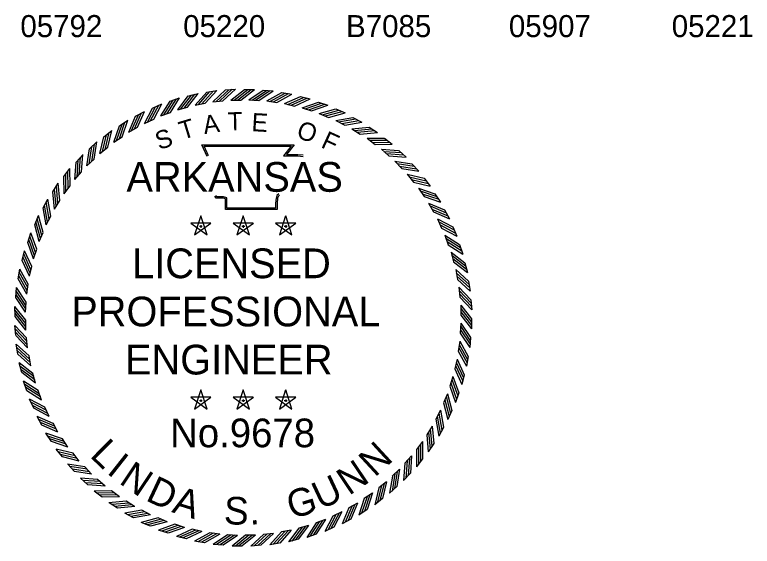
# Model space of a CAD drawing. Extents: x -12863 to 18921, y -8840 to 11152.
# Drawn here: x 13229 to 17244, y -8799 to -5907 of the extents above; entities that cross this region are included whole.
import ezdxf

# ---------------------------------------------------------------- set-up
doc = ezdxf.new("R2010")
doc.units = 0
doc.layers.add('Level 50', color=7, linetype='Continuous')
doc.layers.add('Level 52', color=7, linetype='Continuous')

msp = doc.modelspace()

# ---------------------------------------------------------------- linework, layer by layer
at = {"layer": 'Level 52'}
for p, q in [((14174, -6349), (14226.7, -6335.2)), ((14274.6, -6328.5), (14328.3, -6319)), ((14376.6, -6316.3), (14430.9, -6311.3)), ((14479.8, -6313.2), (14534.3, -6313.2)), ((14581.9, -6317.3), (14636.2, -6321.3)), ((14683.7, -6330.6), (14737.5, -6339)), ((14075.4, -6377.8), (14126.8, -6359.7)), ((14307.9, -6380.8), (14362.3, -6375.8)), ((14405.4, -6371.2), (14460.1, -6371.2)), ((14503.4, -6369.7), (14557.9, -6373.7)), ((14601.2, -6376.3), (14655.2, -6384.8)), ((14784.1, -6352.1), (14837.1, -6365)), ((14882.4, -6382), (14934.1, -6399.2)), ((13979.6, -6414.7), (14029.2, -6392.3)), ((14116.8, -6424), (14169.7, -6410.1)), ((14211.5, -6398.5), (14265.3, -6389)), ((14698.2, -6390.9), (14751.2, -6403.8)), ((14793.5, -6413.5), (14845.4, -6430.7)), ((14977.9, -6419.8), (15028, -6441.2)), ((13887.1, -6459.3), (13934.7, -6432.9)), ((14024.7, -6457.3), (14076.1, -6439.1)), ((14886.7, -6443.8), (14936.9, -6465.3)), ((13798.6, -6511.4), (13843.9, -6481.2)), ((13935.5, -6498.1), (13985.3, -6475.7)), ((14977.1, -6481.8), (15025.4, -6507.4)), ((15069.9, -6465.4), (15118.1, -6490.8)), ((13714.7, -6570.7), (13757.3, -6536.8)), ((13850.1, -6546), (13897.8, -6519.6)), ((15064, -6527.1), (15110, -6556.6)), ((15157.9, -6518.4), (15203.8, -6547.8)), ((13768.8, -6600.9), (13814.3, -6570.6)), ((15146.9, -6579.4), (15190.3, -6612.6)), ((15241.2, -6578.5), (15284.5, -6611.6)), ((13636, -6636.7), (13675.7, -6599.4)), ((13692.4, -6662.3), (13735.2, -6628.4)), ((15225.2, -6638.4), (15265.7, -6675)), ((15319.2, -6645.3), (15359.6, -6681.8)), ((13563, -6708.9), (13599.5, -6668.5)), ((13621.4, -6729.8), (13661.2, -6692.5)), ((15298.3, -6703.7), (15335.7, -6743.5)), ((13496.2, -6787), (13529.2, -6743.7)), ((15391.5, -6718.3), (15428.7, -6758)), ((13556.1, -6803), (13592.7, -6762.4)), ((15365.8, -6774.7), (15399.7, -6817.5)), ((13436.1, -6870.2), (13465.5, -6824.4)), ((15457.4, -6797), (15491.3, -6839.7)), ((13497.1, -6881.2), (13530.3, -6837.8)), ((15427.2, -6851.1), (15457.5, -6896.6)), ((15516.7, -6880.9), (15546.9, -6926.2)), ((13383, -6958.2), (13408.5, -6910)), ((13444.8, -6964.1), (13474.3, -6918.1)), ((15482.1, -6932.4), (15508.5, -6980.1)), ((15568.8, -6969.4), (15595.2, -7017)), ((13337.5, -7050.2), (13358.9, -7000.1)), ((13399.5, -7051), (13425.1, -7002.8)), ((14241.7, -7000.7), (14207.6, -7105.3)), ((14275.7, -7105.2), (14241.8, -7000.6)), ((14472.8, -7000.7), (14438.7, -7105.3)), ((14506.8, -7105.2), (14472.9, -7000.6)), ((14703.9, -7000.7), (14669.8, -7105.3)), ((14737.9, -7105.2), (14704, -7000.6)), ((15530.1, -7017.8), (15552.5, -7067.6)), ((14296.6, -7040.6), (14186.7, -7040.5)), ((14186.7, -7040.6), (14275.7, -7105.4)), ((14207.7, -7105.2), (14296.8, -7040.7)), ((14233.9, -7058.2), (14250.2, -7058.2)), ((14241.8, -7052.3), (14241.8, -7066.1)), ((14527.8, -7040.6), (14417.8, -7040.5)), ((14417.9, -7040.6), (14506.8, -7105.4)), ((14438.8, -7105.2), (14527.9, -7040.7)), ((14465, -7058.2), (14481.3, -7058.2)), ((14472.9, -7052.3), (14472.9, -7066.1)), ((14758.9, -7040.6), (14648.9, -7040.5)), ((14649, -7040.6), (14737.9, -7105.4)), ((14670, -7105.2), (14759, -7040.7)), ((14696.1, -7058.2), (14712.4, -7058.2)), ((14704, -7052.3), (14704, -7066.1)), ((15613.5, -7061.9), (15635.8, -7111.5)), ((13299.6, -7145.7), (13316.9, -7094)), ((13361.5, -7141.4), (13383, -7091.2)), ((15570.9, -7107), (15589.1, -7158.4)), ((13331.2, -7234.6), (13348.4, -7182.8)), ((15650.3, -7157.7), (15668.5, -7209.1)), ((13269.8, -7244), (13282.7, -7191.1)), ((15604.1, -7199.2), (15618, -7252)), ((15679.1, -7256.3), (15693, -7309)), ((13248.2, -7344.4), (13256.7, -7290.6)), ((13308.6, -7330), (13321.5, -7276.9)), ((15629.7, -7293.8), (15639.1, -7347.6)), ((13294, -7426.9), (13302.5, -7372.9)), ((15699.7, -7356.9), (15709.1, -7410.6)), ((13235, -7446.3), (13239, -7391.9)), ((15647.3, -7390.2), (15652.3, -7444.6)), ((15711.9, -7458.9), (15716.9, -7513.2)), ((13230.3, -7548.9), (13229.8, -7494.4)), ((13287.4, -7524.7), (13291.4, -7470.2)), ((15656.9, -7487.7), (15657.4, -7542.4)), ((13288.9, -7622.7), (13288.4, -7568.1)), ((15658.4, -7585.7), (15654.4, -7640.2)), ((15715.6, -7561.6), (15716.1, -7616)), ((13234, -7651.5), (13229, -7597.3)), ((13298.5, -7720.2), (13293.5, -7665.9)), ((15710.8, -7664.2), (15706.8, -7718.5)), ((13246.2, -7753.5), (13236.7, -7699.8)), ((15651.9, -7683.5), (15643.4, -7737.5)), ((13316.2, -7816.7), (13306.7, -7762.9)), ((15637.2, -7780.5), (15624.3, -7833.5)), ((15697.6, -7766), (15689.1, -7819.8)), ((13266.7, -7854.1), (13252.9, -7801.4)), ((13341.7, -7911.3), (13327.8, -7858.5)), ((15676, -7866.4), (15663.1, -7919.4)), ((13295.5, -7952.7), (13277.4, -7901.3)), ((15614.7, -7875.8), (15597.4, -7927.7)), ((14241.7, -7948.3), (14207.6, -8052.9)), ((14275.7, -8052.8), (14241.8, -7948.2)), ((14472.8, -7948.3), (14438.7, -8052.9)), ((14506.8, -8052.8), (14472.9, -7948.2)), ((14703.9, -7948.3), (14669.8, -8052.9)), ((14737.9, -8052.8), (14704, -7948.2)), ((13375, -8003.5), (13356.8, -7952)), ((14296.6, -7988.2), (14186.7, -7988.1)), ((14186.7, -7988.2), (14275.7, -8053)), ((14207.7, -8052.8), (14296.8, -7988.3)), ((14527.8, -7988.2), (14417.8, -7988.1)), ((14417.9, -7988.2), (14506.8, -8053)), ((14438.8, -8052.8), (14527.9, -7988.3)), ((14758.9, -7988.2), (14648.9, -7988.1)), ((14649, -7988.2), (14737.9, -8053)), ((14670, -8052.8), (14759, -7988.3)), ((15584.3, -7969), (15562.8, -8019.2)), ((15646.2, -7964.7), (15629, -8016.4)), ((13332.4, -8048.6), (13310, -7998.9)), ((14233.9, -8005.8), (14250.2, -8005.8)), ((14241.8, -7999.9), (14241.8, -8013.7)), ((14465, -8005.8), (14481.3, -8005.8)), ((14472.9, -7999.9), (14472.9, -8013.7)), ((14696.1, -8005.8), (14712.4, -8005.8)), ((14704, -7999.9), (14704, -8013.7)), ((13415.7, -8092.6), (13393.3, -8042.8)), ((15546.3, -8059.4), (15520.8, -8107.7)), ((15608.4, -8060.2), (15586.9, -8110.3)), ((13377, -8141.1), (13350.6, -8093.4)), ((13463.7, -8178.1), (13437.3, -8130.3)), ((15501, -8146.3), (15471.6, -8192.3)), ((13429.1, -8229.6), (13398.9, -8184.2)), ((15562.8, -8152.2), (15537.3, -8200.4)), ((13518.6, -8259.3), (13488.3, -8213.9)), ((15448.7, -8229.2), (15415.6, -8272.6)), ((13488.4, -8313.5), (13454.5, -8270.8)), ((15509.8, -8240.2), (15480.4, -8286.1)), ((13580, -8335.7), (13546.1, -8292.9)), ((15389.7, -8307.5), (15353.1, -8348)), ((15449.7, -8323.5), (15416.6, -8366.8)), ((13554.4, -8392.2), (13517.1, -8352.4)), ((13647.5, -8406.8), (13610.2, -8366.9)), ((15324.5, -8380.6), (15284.6, -8418)), ((13626.6, -8465.2), (13586.2, -8428.6)), ((15382.9, -8401.5), (15346.3, -8441.9)), ((13720.7, -8472), (13680.1, -8435.4)), ((15253.4, -8448.1), (15210.6, -8482.1)), ((13704.7, -8532), (13661.4, -8498.9)), ((13798.9, -8531), (13755.5, -8497.9)), ((15177, -8509.5), (15131.5, -8539.8)), ((15309.9, -8473.8), (15270.1, -8511)), ((15231.2, -8539.7), (15188.5, -8573.6)), ((13787.9, -8592.1), (13742.1, -8562.7)), ((13881.8, -8583.3), (13835.8, -8553.9)), ((15095.8, -8564.4), (15048, -8590.8)), ((13875.9, -8645.1), (13827.7, -8619.6)), ((13968.7, -8628.6), (13920.5, -8603.1)), ((15010.3, -8612.4), (14960.5, -8634.8)), ((15147.3, -8599), (15101.9, -8629.2)), ((13967.9, -8690.7), (13917.8, -8669.2)), ((14059.1, -8666.6), (14008.9, -8645.1)), ((14921.2, -8653.2), (14869.7, -8671.4)), ((15058.8, -8651.1), (15011.1, -8677.5)), ((14063.4, -8728.5), (14011.7, -8711.3)), ((14152.3, -8697), (14100.5, -8679.7)), ((14247.7, -8719.6), (14194.6, -8706.6)), ((14734.3, -8712), (14680.6, -8721.4)), ((14829, -8686.4), (14776.2, -8700.3)), ((14966.3, -8695.8), (14916.6, -8718.1)), ((14161.7, -8758.3), (14108.8, -8745.4)), ((14344.6, -8734.2), (14290.6, -8725.7)), ((14442.4, -8740.7), (14387.9, -8736.7)), ((14540.4, -8739.2), (14485.8, -8739.7)), ((14637.9, -8729.6), (14583.6, -8734.6)), ((14870.4, -8732.6), (14819, -8750.8)), ((14262.1, -8779.9), (14208.3, -8771.4)), ((14364, -8793.1), (14309.6, -8789.1)), ((14671.2, -8782), (14617.5, -8791.4)), ((14771.8, -8761.4), (14719.1, -8775.3)), ((14466.6, -8797.9), (14412.1, -8798.4)), ((14569.2, -8794.2), (14515, -8799.2))]:
    msp.add_line(p, q, dxfattribs=at)
for points in [[(14152, -6414.6), (14209.1, -6339.6)], [(14169.6, -6410.1), (14226.7, -6335.1)], [(14211.4, -6398.5), (14274.6, -6328.5)], [(14228.7, -6395.7), (14291.9, -6325.6)], [(14247.3, -6392), (14310.4, -6321.9)], [(14265.2, -6389), (14328.3, -6319)], [(14307.8, -6380.9), (14376.5, -6316.3)], [(14325.3, -6379.4), (14394, -6314.9)], [(14344.1, -6377.3), (14412.8, -6312.7)], [(14362.2, -6375.8), (14430.9, -6311.2)], [(14405.4, -6371.3), (14479.7, -6313.3)], [(14422.9, -6371.4), (14497.3, -6313.5)], [(14441.8, -6371), (14516.2, -6313)], [(14460, -6371.2), (14534.3, -6313.2)], [(14503.4, -6369.7), (14581.8, -6317.4)], [(14520.9, -6371.2), (14599.2, -6318.8)], [(14539.8, -6372.2), (14618.2, -6319.8)], [(14557.8, -6373.7), (14636.2, -6321.3)], [(14601.2, -6376.3), (14683.6, -6330.6)], [(14618.5, -6379.2), (14700.9, -6333.5)], [(14637.2, -6381.7), (14719.7, -6336)], [(14655.1, -6384.7), (14737.6, -6339)], [(14024.6, -6457.4), (14075.4, -6377.9)], [(14041.2, -6451.7), (14092, -6372.2)], [(14058.9, -6445), (14109.7, -6365.5)], [(14076.1, -6439.1), (14126.8, -6359.6)], [(14116.8, -6424.1), (14173.9, -6349.1)], [(14133.8, -6419.8), (14190.9, -6344.8)], [(14698.1, -6390.9), (14784, -6352.2)], [(14715.1, -6395.2), (14801, -6356.5)], [(14733.6, -6399.3), (14819.5, -6360.5)], [(14751.2, -6403.8), (14837.1, -6365)], [(14793.5, -6413.5), (14882.3, -6382)], [(13935.5, -6498.1), (13979.5, -6414.8)], [(13951.5, -6491.1), (13995.6, -6407.7)], [(13968.6, -6482.9), (14012.7, -6399.6)], [(13985.3, -6475.6), (14029.3, -6392.3)], [(14810, -6419.2), (14898.9, -6387.7)], [(14828.1, -6424.8), (14917, -6393.3)], [(14845.3, -6430.7), (14934.2, -6399.1)], [(14886.6, -6443.9), (14977.8, -6419.8)], [(13850, -6546.1), (13887, -6459.4)], [(13865.4, -6537.8), (13902.4, -6451.1)], [(13881.8, -6528.2), (13918.8, -6441.5)], [(13897.8, -6519.6), (13934.8, -6432.9)], [(14902.7, -6450.9), (14993.9, -6426.8)], [(14920.3, -6458), (15011.4, -6433.9)], [(14936.9, -6465.3), (15028, -6441.2)], [(13783.5, -6591.4), (13813.2, -6501.9)], [(13799, -6580.6), (13828.7, -6491.1)], [(13814.2, -6570.6), (13843.9, -6481.2)], [(14977, -6481.8), (15069.8, -6465.4)], [(14992.4, -6490.2), (15085.3, -6473.7)], [(15009.4, -6498.7), (15102.2, -6482.2)], [(15025.3, -6507.3), (15118.1, -6490.8)], [(13735.2, -6628.4), (13757.4, -6536.8)], [(13768.8, -6601), (13798.5, -6511.5)], [(15063.9, -6527.1), (15157.8, -6518.4)], [(15078.6, -6536.7), (15172.5, -6528)], [(15094.8, -6546.6), (15188.6, -6537.8)], [(13692.4, -6662.4), (13714.6, -6570.8)], [(13706.3, -6651.6), (13728.5, -6560)], [(13720.8, -6639.5), (13743, -6547.9)], [(15110, -6556.5), (15203.8, -6547.7)], [(15146.8, -6579.4), (15241.1, -6578.5)], [(13634.3, -6718), (13648.8, -6624.9)], [(13647.8, -6704.8), (13662.4, -6611.6)], [(13661.1, -6692.5), (13675.7, -6599.3)], [(14276.8, -6677.9), (14247.8, -6615), (14750.3, -6614.7), (14708.3, -6667.5), (14742.4, -6667), (14770.9, -6666.7), (14799.4, -6669.8)], [(14284, -6674.6), (14260.2, -6623), (14733.7, -6622.7), (14691.6, -6675.6), (14742.5, -6675), (14770.6, -6674.6), (14798.6, -6677.7)], [(15160.6, -6590.2), (15254.9, -6589.2)], [(15175.9, -6601.4), (15270.2, -6600.4)], [(15190.3, -6612.5), (15284.5, -6611.6)], [(13621.4, -6729.9), (13635.9, -6636.8)], [(15225.1, -6638.4), (15319.1, -6645.2)], [(15238, -6650.3), (15332, -6657.1)], [(15252.3, -6662.7), (15346.3, -6669.5)], [(13568, -6790.1), (13574.8, -6696.1)], [(13580.4, -6775.8), (13587.2, -6681.8)], [(13592.7, -6762.5), (13599.5, -6668.4)], [(15265.7, -6675), (15359.7, -6681.8)], [(15298.2, -6703.7), (15391.4, -6718.2)], [(13530.2, -6837.9), (13529.2, -6743.6)], [(13556.1, -6803), (13562.9, -6709)], [(15310.1, -6716.6), (15403.2, -6731.1)], [(15323.4, -6730.1), (15416.5, -6744.7)], [(15335.7, -6743.4), (15428.8, -6758)], [(13507.9, -6867.5), (13506.9, -6773.2)], [(13519.1, -6852.2), (13518.1, -6757.9)], [(15365.7, -6774.7), (15457.4, -6796.9)], [(13474.2, -6918.2), (13465.4, -6824.3)], [(13497.1, -6881.3), (13496.2, -6787.1)], [(15376.5, -6788.6), (15468.1, -6810.8)], [(15388.6, -6803.1), (15480.2, -6825.3)], [(15399.7, -6817.5), (15491.4, -6839.7)], [(13454.4, -6949.5), (13445.7, -6855.7)], [(13464.3, -6933.4), (13455.5, -6839.5)], [(15427.1, -6851.1), (15516.6, -6880.8)], [(15436.7, -6865.8), (15526.2, -6895.5)], [(13444.8, -6964.2), (13436.1, -6870.3)], [(14671.1, -6888.5), (14662.5, -6895.5), (14659.7, -6905.9), (14656.8, -6931.9), (14656.8, -6966.7), (14376.3, -6966.7), (14376.3, -6919.8), (14376.3, -6909.4), (14364.9, -6905.9), (14325, -6905.9), (14317.9, -6895.1)], [(14666, -6882.3), (14655.5, -6890.9), (14651.8, -6904.4), (14648.9, -6931.5), (14648.9, -6958.7), (14384.3, -6958.7), (14384.3, -6919.8), (14384.3, -6903.5), (14366.1, -6897.9), (14329.3, -6897.9), (14324.6, -6890.7)], [(15447.6, -6881.3), (15537, -6911)], [(15457.5, -6896.5), (15547, -6926.2)], [(13407.9, -7035.7), (13391.4, -6942.9)], [(13416.4, -7018.8), (13399.9, -6925.9)], [(13425, -7002.8), (13408.5, -6910)], [(15482, -6932.3), (15568.7, -6969.3)], [(13399.5, -7051.1), (13383.1, -6958.3)], [(15490.4, -6947.7), (15577.1, -6984.7)], [(15499.9, -6964.1), (15586.6, -7001.1)], [(15508.5, -6980.1), (15595.2, -7017.1)], [(13375.7, -7107.9), (13351.6, -7016.7)], [(13383, -7091.2), (13358.9, -7000.1)], [(15530, -7017.8), (15613.4, -7061.8)], [(13361.6, -7141.5), (13337.5, -7050.3)], [(13368.6, -7125.4), (13344.5, -7034.3)], [(15537.1, -7033.8), (15620.4, -7077.9)], [(15545.2, -7050.9), (15628.6, -7095)], [(13348.4, -7182.8), (13316.8, -7094)], [(15552.5, -7067.6), (15635.9, -7111.6)], [(15570.8, -7106.9), (15650.2, -7157.7)], [(13331.2, -7234.7), (13299.7, -7145.8)], [(13336.9, -7218.1), (13305.4, -7129.2)], [(13342.5, -7200), (13310.9, -7111.1)], [(15576.5, -7123.5), (15655.9, -7174.3)], [(15583.2, -7141.2), (15662.6, -7192)], [(15589.1, -7158.4), (15668.5, -7209.1)], [(13312.9, -7313.1), (13274.2, -7227.1)], [(13317, -7294.6), (13278.2, -7208.6)], [(13321.4, -7277), (13282.7, -7191)], [(15604.1, -7199.1), (15679, -7256.2)], [(15608.4, -7216.1), (15683.3, -7273.3)], [(13308.6, -7330.1), (13269.9, -7244.1)], [(15613.6, -7234.3), (15688.6, -7291.4)], [(15618, -7251.9), (15693, -7309)], [(13302.4, -7373), (13256.7, -7290.6)], [(15629.6, -7293.7), (15699.6, -7356.9)], [(13294, -7427), (13248.3, -7344.5)], [(13296.9, -7409.7), (13251.2, -7327.2)], [(13299.4, -7390.9), (13253.7, -7308.5)], [(15632.5, -7311), (15702.5, -7374.2)], [(15636.2, -7329.6), (15706.2, -7392.7)], [(15639.2, -7347.5), (15709.2, -7410.6)], [(13289.9, -7488.4), (13237.5, -7410)], [(13291.4, -7470.3), (13239, -7391.9)], [(15647.2, -7390.1), (15711.8, -7458.8)], [(15648.7, -7407.6), (15713.2, -7476.3)], [(15650.8, -7426.4), (15715.4, -7495.1)], [(13287.4, -7524.8), (13235.1, -7446.4)], [(13288.9, -7507.3), (13236.5, -7428.9)], [(15652.3, -7444.5), (15716.9, -7513.2)], [(13288.4, -7568.2), (13229.7, -7494.3)], [(15656.9, -7487.7), (15715.5, -7561.5)], [(15656.9, -7505.2), (15715.5, -7579)], [(13288.4, -7586.3), (13229.7, -7512.5)], [(13289, -7605.2), (13230.3, -7531.4)], [(15657.5, -7524.1), (15716.1, -7597.9)], [(15657.5, -7542.3), (15716.1, -7616.1)], [(13289, -7622.8), (13230.3, -7549)], [(15658.4, -7585.7), (15710.8, -7664.1)], [(13293.5, -7665.9), (13228.9, -7597.2)], [(13295, -7684), (13230.4, -7615.3)], [(15656, -7622.1), (15708.3, -7700.5)], [(15656.9, -7603.2), (15709.3, -7681.6)], [(13297.1, -7702.8), (13232.6, -7634.1)], [(13298.6, -7720.3), (13234, -7651.6)], [(15654.5, -7640.2), (15706.8, -7718.5)], [(13306.7, -7762.9), (13236.7, -7699.8)], [(15648.9, -7700.8), (15694.7, -7783.2)], [(15651.8, -7683.5), (15697.5, -7765.9)], [(13309.6, -7780.8), (13239.6, -7717.7)], [(13313.3, -7799.4), (13243.3, -7736.3)], [(15643.4, -7737.4), (15689.1, -7819.9)], [(15646.4, -7719.5), (15692.1, -7802)], [(13316.2, -7816.7), (13246.2, -7753.6)], [(15637.2, -7780.4), (15676, -7866.3)], [(13327.8, -7858.5), (13252.8, -7801.4)], [(13332.3, -7876.1), (13257.3, -7819)], [(15628.8, -7815.9), (15667.6, -7901.8)], [(15632.9, -7797.4), (15671.7, -7883.3)], [(13337.5, -7894.3), (13262.5, -7837.2)], [(13341.8, -7911.3), (13266.8, -7854.2)], [(15624.4, -7833.5), (15663.1, -7919.4)], [(13356.8, -7952.1), (13277.3, -7901.3)], [(15608.9, -7892.4), (15640.5, -7981.2)], [(15614.6, -7875.8), (15646.2, -7964.6)], [(13362.6, -7969.2), (13283.2, -7918.5)], [(13369.4, -7986.9), (13289.9, -7936.2)], [(15597.5, -7927.6), (15629, -8016.5)], [(15603.4, -7910.4), (15634.9, -7999.3)], [(13375, -8003.5), (13295.6, -7952.8)], [(15577.2, -7985), (15601.3, -8076.2)], [(15584.3, -7969), (15608.3, -8060.1)], [(13393.3, -8042.9), (13310, -7998.9)], [(13400.6, -8059.5), (13317.3, -8015.5)], [(15562.9, -8019.2), (15587, -8110.4)], [(15570.2, -8002.6), (15594.2, -8093.7)], [(13408.8, -8076.6), (13325.4, -8032.6)], [(13415.8, -8092.7), (13332.5, -8048.6)], [(15546.3, -8059.3), (15562.8, -8152.1)], [(13437.3, -8130.4), (13350.6, -8093.4)], [(13445.9, -8146.3), (13359.2, -8109.3)], [(15520.8, -8107.6), (15537.3, -8200.5)], [(15529.5, -8091.7), (15545.9, -8184.5)], [(15538, -8074.7), (15554.4, -8167.6)], [(13455.5, -8162.7), (13368.7, -8125.7)], [(13463.8, -8178.1), (13377.1, -8141.1)], [(15501, -8146.2), (15509.8, -8240.1)], [(13488.3, -8213.9), (13398.9, -8184.2)], [(15481.6, -8177.1), (15490.3, -8271)], [(15491.4, -8160.9), (15500.2, -8254.8)], [(13498.3, -8229.1), (13408.8, -8199.4)], [(13509.1, -8244.6), (13419.6, -8214.9)], [(13518.7, -8259.3), (13429.2, -8229.6)], [(15448.7, -8229.1), (15449.7, -8323.4)], [(15471.6, -8192.3), (15480.4, -8286.1)], [(13546.1, -8293), (13454.5, -8270.8)], [(15426.8, -8258.3), (15427.7, -8352.5)], [(15437.9, -8243), (15438.9, -8337.2)], [(13557.2, -8307.3), (13465.6, -8285.1)], [(13569.3, -8321.9), (13477.7, -8299.7)], [(15389.7, -8307.4), (15382.9, -8401.4)], [(15415.6, -8272.6), (15416.6, -8366.8)], [(13580.1, -8335.7), (13488.5, -8313.5)], [(15353.2, -8348), (15346.3, -8442)], [(15365.5, -8334.6), (15358.6, -8428.6)], [(15377.8, -8320.3), (15371, -8414.3)], [(13610.2, -8367), (13517, -8352.4)], [(13622.5, -8380.4), (13529.3, -8365.8)], [(13635.7, -8393.9), (13542.6, -8379.3)], [(15324.5, -8380.5), (15309.9, -8473.7)], [(13647.6, -8406.8), (13554.5, -8392.2)], [(13680.2, -8435.5), (13586.1, -8428.6)], [(15284.7, -8418), (15270.1, -8511.1)], [(15298, -8405.7), (15283.5, -8498.8)], [(15311.6, -8392.4), (15297, -8485.6)], [(13693.5, -8447.8), (13599.5, -8440.9)], [(13707.8, -8460.1), (13613.8, -8453.3)], [(13720.7, -8472), (13626.7, -8465.2)], [(15225, -8470.9), (15202.8, -8562.5)], [(15239.6, -8458.8), (15217.4, -8550.4)], [(15253.4, -8448), (15231.2, -8539.7)], [(13755.6, -8497.9), (13661.3, -8498.9)], [(13769.9, -8509.1), (13675.6, -8510)], [(15177, -8509.4), (15147.3, -8598.9)], [(15210.7, -8482), (15188.5, -8573.7)], [(13785.2, -8520.2), (13690.9, -8521.2)], [(13799, -8531), (13704.7, -8532)], [(15131.6, -8539.8), (15101.9, -8629.3)], [(15146.8, -8529.9), (15117.1, -8619.4)], [(15162.3, -8519), (15132.6, -8608.5)], [(13835.9, -8553.9), (13742, -8562.7)], [(13851.1, -8563.9), (13757.2, -8572.6)], [(13867.2, -8573.7), (13773.3, -8582.5)], [(13881.9, -8583.3), (13788, -8592.1)], [(15048.1, -8590.8), (15011.1, -8677.6)], [(15064, -8582.2), (15027, -8668.9)], [(15080.4, -8572.7), (15043.4, -8659.4)], [(15095.8, -8564.3), (15058.8, -8651)], [(13920.5, -8603.1), (13827.7, -8619.6)], [(13936.5, -8611.8), (13843.6, -8628.2)], [(13953.4, -8620.3), (13860.6, -8636.7)], [(13968.8, -8628.6), (13876, -8645.1)], [(14977.2, -8627.5), (14933.2, -8710.9)], [(14994.3, -8619.4), (14950.3, -8702.7)], [(15010.4, -8612.3), (14966.3, -8695.7)], [(14008.9, -8645.2), (13917.8, -8669.3)], [(14025.6, -8652.5), (13934.4, -8676.5)], [(14043.1, -8659.5), (13952, -8683.6)], [(14059.2, -8666.6), (13968, -8690.7)], [(14869.8, -8671.4), (14819, -8750.8)], [(14886.9, -8665.5), (14836.2, -8744.9)], [(14904.6, -8658.8), (14853.9, -8738.2)], [(14921.2, -8653.1), (14870.5, -8732.5)], [(14960.6, -8634.8), (14916.6, -8718.2)], [(14100.5, -8679.8), (14011.7, -8711.3)], [(14117.7, -8685.7), (14028.8, -8717.2)], [(14135.8, -8691.3), (14046.9, -8722.8)], [(14152.4, -8696.9), (14063.5, -8728.5)], [(14194.7, -8706.7), (14108.7, -8745.4)], [(14212.3, -8711.1), (14126.3, -8749.9)], [(14734.4, -8711.9), (14671.3, -8781.9)], [(14776.2, -8700.3), (14719.1, -8775.3)], [(14793.8, -8695.9), (14736.7, -8770.9)], [(14812, -8690.7), (14754.9, -8765.6)], [(14829, -8686.4), (14771.9, -8761.3)], [(14230.7, -8715.2), (14144.8, -8754)], [(14247.7, -8719.5), (14161.8, -8758.3)], [(14290.7, -8725.7), (14208.2, -8771.4)], [(14308.6, -8728.7), (14226.2, -8774.4)], [(14327.4, -8731.2), (14244.9, -8777)], [(14344.7, -8734.1), (14262.2, -8779.8)], [(14388, -8736.8), (14309.6, -8789.1)], [(14406.1, -8738.3), (14327.7, -8790.6)], [(14425, -8739.3), (14346.6, -8791.6)], [(14442.5, -8740.7), (14364.1, -8793.1)], [(14485.8, -8739.8), (14412, -8798.4)], [(14504, -8739.8), (14430.2, -8798.4)], [(14522.9, -8739.2), (14449.1, -8797.8)], [(14540.5, -8739.2), (14466.7, -8797.8)], [(14583.6, -8734.6), (14514.9, -8799.2)], [(14601.7, -8733.1), (14533, -8797.7)], [(14620.5, -8731), (14551.8, -8795.5)], [(14638, -8729.5), (14569.3, -8794.1)], [(14680.6, -8721.5), (14617.5, -8791.5)], [(14698.5, -8718.5), (14635.4, -8788.5)], [(14717.1, -8714.8), (14654, -8784.8)]]:
    msp.add_lwpolyline(points, dxfattribs=at)

# ---------------------------------------------------------------- texts
at = {"layer": 'Level 50'}
for s, p in [('05792', (13259.5, -6028.9)), ('05220', (14146.1, -6028.9)), ('B7085', (15032.6, -6028.9)), ('05907', (15919.2, -6028.9)), ('05221', (16805.8, -6028.9))]:
    msp.add_text(s, height=120, dxfattribs=at).set_placement(p)
at = {"layer": 'Level 52'}
for s, height, rotation, p in [('A', 99.1, 8.6788, (14261.5, -6556.9)), ('T', 99.1, 1.4789, (14389.5, -6537.2)), ('E', 99.1, 356.672, (14516.3, -6540.2)), ('T', 99.1, 16.9015, (14141.1, -6588.4)), ('O', 99.1, 341.2218, (14757, -6574.2)), ('S', 99.1, 19.7726, (14015.1, -6644.9)), ('F', 99.1, 335.3628, (14890.6, -6626.5)), ('L', 150.5, 315.1295, (13633.3, -8308.4)), ('N', 150.5, 42.6817, (15189.2, -8427.4)), ('I', 150.5, 321.696, (13724.8, -8399.5)), ('N', 150.5, 326.0736, (13791.4, -8454.2)), ('N', 150.5, 33.9264, (15048.3, -8526.2)), ('D', 150.5, 334.8288, (13936.1, -8547.5)), ('U', 150.5, 25.1712, (14893.9, -8602.4)), ('A', 150.5, 342.8544, (14079.8, -8612.8)), ('G', 150.5, 16.7808, (14736.7, -8652.6)), ('S', 150.5, 357.8112, (14365.9, -8678.6)), ('.', 150.5, 5.1072, (14509.3, -8683.2))]:
    msp.add_text(s, height=height, rotation=rotation, dxfattribs=at).set_placement(p)
for s, height, p in [('ARKANSAS', 161.78, (13837, -6870.4)), ('LICENSED', 161.78, (13867.8, -7340.6)), ('PROFESSIONAL', 161.779, (13536.5, -7602.6)), ('ENGINEER', 161.78, (13829.3, -7864.5)), ('No.9678', 156, (14075.1, -8260.5))]:
    msp.add_text(s, height=height, dxfattribs=at).set_placement(p)

doc.saveas('drawing.dxf')
